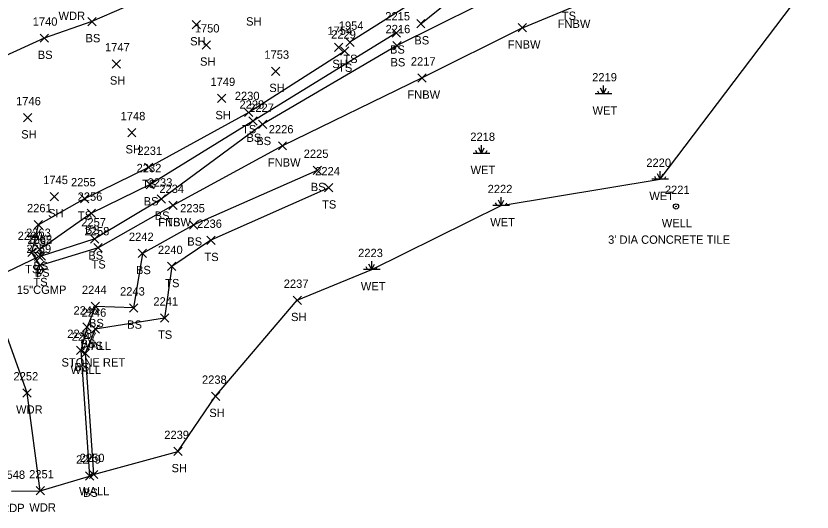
# Model space of a CAD drawing. Extents: x 1526508 to 1531550, y 369926 to 373082.
# Drawn here: x 1531142.8 to 1531334.3, y 370023.7 to 370143.1 of the extents above; entities that cross this region are included whole.
import ezdxf

# ---------------------------------------------------------------- set-up
doc = ezdxf.new("R2010")
doc.units = 0
for name, color, linetype in [('D_A', 7, 'Continuous'), ('D_C', 7, 'Continuous'), ('D_I', 7, 'Continuous'), ('D_TIC', 7, 'Continuous'), ('DCP', 7, 'Continuous'), ('L_A', 7, 'Continuous'), ('L_C', 7, 'Continuous'), ('L_I', 7, 'Continuous'), ('L_TIC', 7, 'Continuous'), ('LAWA', 7, 'Continuous'), ('LELB', 7, 'Continuous'), ('LFNC', 7, 'Continuous'), ('LSOGP', 7, 'Continuous'), ('LW', 7, 'Continuous'), ('LWET', 7, 'Continuous'), ('P_A', 7, 'Continuous'), ('P_I', 7, 'Continuous'), ('U_A', 7, 'Continuous'), ('U_C', 7, 'Continuous'), ('U_I', 7, 'Continuous'), ('UWW', 7, 'Continuous')]:
    doc.layers.add(name, color=color, linetype=linetype)

msp = doc.modelspace()

# ---------------------------------------------------------------- linework, layer by layer
at = {"layer": 'D_TIC'}
for points in [[(1531147.27, 370084.19), (1531149.27, 370086.19)], [(1531149.27, 370084.19), (1531147.27, 370086.19)]]:
    msp.add_lwpolyline(points, dxfattribs=at)
at = {"layer": 'DCP'}
msp.add_lwpolyline([(1531096.61, 370060.47), (1531148.27, 370085.19)], dxfattribs=at)
at = {"layer": 'L_TIC'}
for points in [[(1531160.06, 370140.76), (1531162.06, 370142.76)], [(1531162.06, 370140.76), (1531160.06, 370142.76)], [(1531185.18, 370140.01), (1531187.18, 370142.01)], [(1531187.18, 370140.01), (1531185.18, 370142.01)], [(1531239.15, 370140.24), (1531241.15, 370142.24)], [(1531241.15, 370140.24), (1531239.15, 370142.24)], [(1531263.6, 370139.25), (1531265.6, 370141.25)], [(1531265.6, 370139.25), (1531263.6, 370141.25)], [(1531233.29, 370138.03), (1531235.29, 370140.03)], [(1531235.29, 370138.03), (1531233.29, 370140.03)], [(1531148.58, 370136.75), (1531150.58, 370138.75)], [(1531150.58, 370136.75), (1531148.58, 370138.75)], [(1531187.55, 370135.12), (1531189.55, 370137.12)], [(1531189.55, 370135.12), (1531187.55, 370137.12)], [(1531222.1, 370135.77), (1531224.1, 370137.77)], [(1531224.1, 370135.77), (1531222.1, 370137.77)], [(1531219.37, 370134.56), (1531221.37, 370136.56)], [(1531221.37, 370134.56), (1531219.37, 370136.56)], [(1531220.84, 370133.65), (1531222.84, 370135.65)], [(1531222.84, 370133.65), (1531220.84, 370135.65)], [(1531233.42, 370134.95), (1531235.42, 370136.95)], [(1531235.42, 370134.95), (1531233.42, 370136.95)], [(1531165.88, 370130.57), (1531167.88, 370132.57)], [(1531167.88, 370130.57), (1531165.88, 370132.57)], [(1531204.21, 370128.79), (1531206.21, 370130.79)], [(1531206.21, 370128.79), (1531204.21, 370130.79)], [(1531239.44, 370127.17), (1531241.44, 370129.17)], [(1531241.44, 370127.17), (1531239.44, 370129.17)], [(1531191.25, 370122.24), (1531193.25, 370124.24)], [(1531193.25, 370122.24), (1531191.25, 370124.24)], [(1531197.75, 370118.86), (1531199.75, 370120.86)], [(1531199.75, 370118.86), (1531197.75, 370120.86)], [(1531144.55, 370117.6), (1531146.55, 370119.6)], [(1531146.55, 370117.6), (1531144.55, 370119.6)], [(1531198.78, 370116.78), (1531200.78, 370118.78)], [(1531200.78, 370116.78), (1531198.78, 370118.78)], [(1531201.13, 370116.01), (1531203.13, 370118.01)], [(1531203.13, 370116.01), (1531201.13, 370118.01)], [(1531169.64, 370114), (1531171.64, 370116)], [(1531171.64, 370114), (1531169.64, 370116)], [(1531205.88, 370110.83), (1531207.88, 370112.83)], [(1531207.88, 370110.83), (1531205.88, 370112.83)], [(1531173.68, 370105.65), (1531175.68, 370107.65)], [(1531175.68, 370105.65), (1531173.68, 370107.65)], [(1531214.23, 370104.93), (1531216.23, 370106.93)], [(1531216.23, 370104.93), (1531214.23, 370106.93)], [(1531174.05, 370101.49), (1531176.05, 370103.49)], [(1531176.05, 370101.49), (1531174.05, 370103.49)], [(1531216.99, 370100.73), (1531218.99, 370102.73)], [(1531218.99, 370100.73), (1531216.99, 370102.73)], [(1531151.01, 370098.62), (1531153.01, 370100.62)], [(1531153.01, 370098.62), (1531151.01, 370100.62)], [(1531158.26, 370098.08), (1531160.26, 370100.08)], [(1531160.26, 370098.08), (1531158.26, 370100.08)], [(1531176.7, 370098.03), (1531178.7, 370100.03)], [(1531178.7, 370098.03), (1531176.7, 370100.03)], [(1531179.52, 370096.48), (1531181.52, 370098.48)], [(1531181.52, 370096.48), (1531179.52, 370098.48)], [(1531179.52, 370096.48), (1531181.52, 370098.48)], [(1531181.52, 370096.48), (1531179.52, 370098.48)], [(1531159.93, 370094.61), (1531161.93, 370096.61)], [(1531161.93, 370094.61), (1531159.93, 370096.61)], [(1531147.18, 370091.85), (1531149.18, 370093.85)], [(1531149.18, 370091.85), (1531147.18, 370093.85)], [(1531147.18, 370091.85), (1531149.18, 370093.85)], [(1531149.18, 370091.85), (1531147.18, 370093.85)], [(1531184.52, 370091.81), (1531186.52, 370093.81)], [(1531186.52, 370091.81), (1531184.52, 370093.81)], [(1531160.73, 370088.44), (1531162.73, 370090.44)], [(1531162.73, 370088.44), (1531160.73, 370090.44)], [(1531188.68, 370088.09), (1531190.68, 370090.09)], [(1531190.68, 370088.09), (1531188.68, 370090.09)], [(1531147.5, 370085.91), (1531149.5, 370087.91)], [(1531149.5, 370085.91), (1531147.5, 370087.91)], [(1531147.5, 370085.91), (1531149.5, 370087.91)], [(1531149.5, 370085.91), (1531147.5, 370087.91)], [(1531161.53, 370086.3), (1531163.53, 370088.3)], [(1531163.53, 370086.3), (1531161.53, 370088.3)], [(1531145.59, 370085.17), (1531147.59, 370087.17)], [(1531147.59, 370085.17), (1531145.59, 370087.17)], [(1531147.84, 370084.31), (1531149.84, 370086.31)], [(1531149.84, 370084.31), (1531147.84, 370086.31)], [(1531172.2, 370084.94), (1531174.2, 370086.94)], [(1531174.2, 370084.94), (1531172.2, 370086.94)], [(1531147.56, 370082.05), (1531149.56, 370084.05)], [(1531149.56, 370082.05), (1531147.56, 370084.05)], [(1531179.26, 370081.79), (1531181.26, 370083.79)], [(1531181.26, 370081.79), (1531179.26, 370083.79)], [(1531160.89, 370072.17), (1531162.89, 370074.17)], [(1531162.89, 370072.17), (1531160.89, 370074.17)], [(1531209.44, 370073.64), (1531211.44, 370075.64)], [(1531211.44, 370073.64), (1531209.44, 370075.64)], [(1531170.07, 370071.8), (1531172.07, 370073.8)], [(1531172.07, 370071.8), (1531170.07, 370073.8)], [(1531177.52, 370069.38), (1531179.52, 370071.38)], [(1531179.52, 370069.38), (1531177.52, 370071.38)], [(1531158.87, 370067.22), (1531160.87, 370069.22)], [(1531160.87, 370067.22), (1531158.87, 370069.22)], [(1531160.86, 370066.7), (1531162.86, 370068.7)], [(1531162.86, 370066.7), (1531160.86, 370068.7)], [(1531160.86, 370066.7), (1531162.86, 370068.7)], [(1531162.86, 370066.7), (1531160.86, 370068.7)], [(1531157.37, 370061.59), (1531159.37, 370063.59)], [(1531159.37, 370061.59), (1531157.37, 370063.59)], [(1531158.43, 370060.89), (1531160.43, 370062.89)], [(1531160.43, 370060.89), (1531158.43, 370062.89)], [(1531144.43, 370051.36), (1531146.43, 370053.36)], [(1531146.43, 370051.36), (1531144.43, 370053.36)], [(1531189.78, 370050.55), (1531191.78, 370052.55)], [(1531191.78, 370050.55), (1531189.78, 370052.55)], [(1531180.71, 370037.25), (1531182.71, 370039.25)], [(1531182.71, 370037.25), (1531180.71, 370039.25)], [(1531160.45, 370031.71), (1531162.45, 370033.71)], [(1531162.45, 370031.71), (1531160.45, 370033.71)], [(1531159.49, 370031.33), (1531161.49, 370033.33)], [(1531161.49, 370031.33), (1531159.49, 370033.33)], [(1531147.63, 370027.78), (1531149.63, 370029.78)], [(1531149.63, 370027.78), (1531147.63, 370029.78)]]:
    msp.add_lwpolyline(points, dxfattribs=at)
at = {"layer": 'LAWA'}
msp.add_lwpolyline([(1531148.63, 370028.78), (1531145.43, 370052.36), (1531135.56, 370079.96), (1531135.23, 370090.89)], dxfattribs=at)
at = {"layer": 'LELB'}
for points in [[(1531365.84, 370210.96), (1531346.81, 370202.24), (1531320.04, 370188.54), (1531298.98, 370175.8), (1531270.91, 370160.47), (1531253.9, 370156.3), (1531223.1, 370136.77)], [(1531240.15, 370141.24), (1531255.53, 370153.74), (1531283.26, 370165.55), (1531305.03, 370178.46), (1531329.23, 370188.15), (1531348.16, 370200.01), (1531367.42, 370209.81)], [(1531210.97, 370157.64), (1531190.22, 370151.95), (1531176.55, 370148.6), (1531161.06, 370141.76), (1531149.58, 370137.75), (1531135.28, 370131.25)], [(1531263.26, 370150.37), (1531234.42, 370135.95), (1531202.13, 370117.01), (1531177.7, 370099.03), (1531161.73, 370089.44), (1531148.84, 370085.31), (1531148.5, 370086.91)], [(1531234.29, 370139.03), (1531199.78, 370117.78), (1531175.05, 370102.49), (1531160.93, 370095.61), (1531148.5, 370086.91)], [(1531221.84, 370134.65), (1531198.75, 370119.86), (1531174.68, 370106.65), (1531159.26, 370099.08), (1531148.18, 370092.85)], [(1531215.23, 370105.93), (1531185.52, 370092.81), (1531173.2, 370085.94), (1531171.07, 370072.8), (1531161.89, 370073.17), (1531159.87, 370068.22), (1531158.37, 370062.59), (1531160.49, 370032.33)], [(1531217.99, 370101.73), (1531189.68, 370089.09), (1531180.26, 370082.79), (1531178.52, 370070.38), (1531161.86, 370067.7)], [(1531180.52, 370097.48), (1531162.53, 370087.3), (1531148.56, 370083.05), (1531146.59, 370086.17), (1531148.18, 370092.85)]]:
    msp.add_lwpolyline(points, dxfattribs=at)
at = {"layer": 'LFNC'}
for points in [[(1531264.6, 370140.25), (1531276.59, 370145.24)], [(1531264.6, 370140.25), (1531240.44, 370128.17), (1531206.88, 370111.83), (1531180.52, 370097.48)]]:
    msp.add_lwpolyline(points, dxfattribs=at)
at = {"layer": 'LSOGP'}
msp.add_lwpolyline([(1531141.72, 370028.66), (1531148.63, 370028.78), (1531160.49, 370032.33), (1531161.45, 370032.71), (1531181.71, 370038.25), (1531190.78, 370051.55), (1531210.44, 370074.64), (1531228.34, 370082.05), (1531259.48, 370097.44), (1531297.73, 370103.77), (1531345.31, 370166.81)], dxfattribs=at)
at = {"layer": 'LW'}
msp.add_lwpolyline([(1531161.86, 370067.7), (1531159.43, 370061.89), (1531161.45, 370032.71)], dxfattribs=at)
at = {"layer": 'LWET'}
for p, q in [((1531284.06, 370124.35), (1531283.39, 370125.68)), ((1531284.06, 370124.35), (1531284.06, 370126.35)), ((1531284.06, 370124.35), (1531284.73, 370125.68)), ((1531286.06, 370124.35), (1531282.06, 370124.35)), ((1531283.06, 370124.35), (1531282.73, 370125.01)), ((1531285.06, 370124.35), (1531285.39, 370125.01)), ((1531253.74, 370110.02), (1531253.41, 370110.69)), ((1531254.74, 370110.02), (1531254.07, 370111.35)), ((1531254.74, 370110.02), (1531254.74, 370112.02)), ((1531254.74, 370110.02), (1531255.41, 370111.35)), ((1531255.74, 370110.02), (1531256.07, 370110.69)), ((1531256.74, 370110.02), (1531252.74, 370110.02)), ((1531297.73, 370103.77), (1531297.06, 370105.11)), ((1531297.73, 370103.77), (1531297.73, 370105.77)), ((1531297.73, 370103.77), (1531298.4, 370105.11)), ((1531299.73, 370103.77), (1531295.73, 370103.77)), ((1531296.73, 370103.77), (1531296.4, 370104.44)), ((1531298.73, 370103.77), (1531299.06, 370104.44)), ((1531259.48, 370097.44), (1531258.81, 370098.78)), ((1531259.48, 370097.44), (1531259.48, 370099.44)), ((1531259.48, 370097.44), (1531260.14, 370098.78)), ((1531261.48, 370097.44), (1531257.48, 370097.44)), ((1531258.48, 370097.44), (1531258.14, 370098.11)), ((1531260.48, 370097.44), (1531260.81, 370098.11)), ((1531228.34, 370082.05), (1531228.34, 370084.05)), ((1531230.34, 370082.05), (1531226.34, 370082.05)), ((1531227.34, 370082.05), (1531227.01, 370082.72)), ((1531228.34, 370082.05), (1531227.68, 370083.38)), ((1531228.34, 370082.05), (1531229.01, 370083.38)), ((1531229.34, 370082.05), (1531229.68, 370082.72))]:
    msp.add_line(p, q, dxfattribs=at)
at = {"layer": 'UWW'}
for radius in [0.625, 0.0833]:
    msp.add_circle((1531301.53, 370097.25), radius, dxfattribs=at)

# ---------------------------------------------------------------- texts
at = {"layer": 'D_A'}
msp.add_text('P', height=2, dxfattribs=at).set_placement((1531147.65, 370080.19))
at = {"layer": 'D_C'}
msp.add_text('15"CGMP', height=2, dxfattribs=at).set_placement((1531142.97, 370076.19))
at = {"layer": 'D_I'}
msp.add_text('1565', height=2, dxfattribs=at).set_placement((1531145.53, 370088.19))
at = {"layer": 'L_A'}
for s, p in [('WDR', (1531153.01, 370142.14)), ('SH', (1531198.12, 370140.79)), ('TS', (1531274.06, 370142.15)), ('FNBW', (1531273.06, 370140.24)), ('BS', (1531159.5, 370136.76)), ('SH', (1531184.67, 370136.01)), ('BS', (1531238.59, 370136.24)), ('FNBW', (1531261.07, 370135.25)), ('BS', (1531232.73, 370134.03)), ('BS', (1531148.02, 370132.75)), ('TS', (1531221.51, 370131.77)), ('SH', (1531187.04, 370131.12)), ('SH', (1531218.86, 370130.56)), ('TS', (1531220.25, 370129.65)), ('BS', (1531232.86, 370130.95)), ('SH', (1531165.37, 370126.57)), ('SH', (1531203.7, 370124.79)), ('FNBW', (1531236.92, 370123.17)), ('SH', (1531190.74, 370118.24)), ('WET', (1531281.44, 370119.35)), ('TS', (1531197.16, 370114.86)), ('SH', (1531144.04, 370113.6)), ('BS', (1531198.22, 370112.78)), ('BS', (1531200.57, 370112.01)), ('SH', (1531169.12, 370110)), ('FNBW', (1531203.36, 370106.83)), ('WET', (1531252.12, 370105.02)), ('TS', (1531173.08, 370101.65)), ('BS', (1531213.68, 370100.93)), ('WET', (1531295.11, 370098.77)), ('BS', (1531173.49, 370097.49)), ('TS', (1531216.4, 370096.73)), ('SH', (1531150.5, 370094.62)), ('TS', (1531157.67, 370094.08)), ('BS', (1531176.14, 370094.03)), ('FNBW', (1531176.99, 370092.48)), ('TS', (1531178.93, 370092.48)), ('WET', (1531256.85, 370092.44)), ('BS', (1531159.37, 370090.61)), ('TS', (1531146.58, 370087.85)), ('TS', (1531146.58, 370087.85)), ('BS', (1531183.97, 370087.81)), ('BS', (1531160.17, 370084.44)), ('TS', (1531188.09, 370084.09)), ('BS', (1531146.95, 370081.91)), ('BS', (1531146.95, 370081.91)), ('TS', (1531160.94, 370082.3)), ('TS', (1531144.99, 370081.17)), ('BS', (1531147.28, 370080.31)), ('BS', (1531171.64, 370080.94)), ('TS', (1531146.97, 370078.05)), ('TS', (1531178.67, 370077.79)), ('WET', (1531225.72, 370077.05)), ('BS', (1531160.33, 370068.17)), ('SH', (1531208.93, 370069.64)), ('BS', (1531169.51, 370067.8)), ('TS', (1531176.93, 370065.38)), ('WALL', (1531158.35, 370062.7)), ('BS', (1531158.31, 370063.22)), ('TS', (1531160.27, 370062.7)), ('WALL', (1531155.92, 370056.89)), ('BS', (1531156.81, 370057.59)), ('WDR', (1531142.8, 370047.36)), ('SH', (1531189.27, 370046.55)), ('SH', (1531180.2, 370033.25)), ('WALL', (1531157.94, 370027.71)), ('BS', (1531158.93, 370027.33)), ('WDR', (1531145.99, 370023.78))]:
    msp.add_text(s, height=2, dxfattribs=at).set_placement(p)
at = {"layer": 'L_C'}
msp.add_text('STONE RET', height=2, dxfattribs=at).set_placement((1531153.73, 370058.7))
at = {"layer": 'L_I'}
for s, p in [('2215', (1531231.6, 370142.03)), ('1740', (1531146.8, 370140.75)), ('1750', (1531185.77, 370139.12)), ('1954', (1531220.41, 370139.77)), ('2216', (1531231.67, 370138.95)), ('1754', (1531217.68, 370138.56)), ('2229', (1531218.57, 370137.65)), ('1747', (1531164.19, 370134.57)), ('1753', (1531202.52, 370132.79)), ('2217', (1531237.75, 370131.17)), ('1749', (1531189.55, 370126.24)), ('2219', (1531281.36, 370127.35)), ('2230', (1531195.4, 370122.86)), ('1746', (1531142.8, 370121.6)), ('2228', (1531196.52, 370120.78)), ('2227', (1531198.87, 370120.01)), ('1748', (1531167.94, 370118)), ('2226', (1531203.57, 370114.83)), ('2218', (1531252.05, 370113.02)), ('2231', (1531171.98, 370109.65)), ('2225', (1531211.98, 370108.93)), ('2220', (1531294.38, 370106.77)), ('2232', (1531171.79, 370105.49)), ('2224', (1531214.74, 370104.73)), ('1745', (1531149.32, 370102.62)), ('2255', (1531156.01, 370102.08)), ('2233', (1531174.44, 370102.03)), ('2234', (1531177.26, 370100.48)), ('2234', (1531177.26, 370100.48)), ('2222', (1531256.22, 370100.44)), ('2256', (1531157.61, 370098.61)), ('2261', (1531145.43, 370095.85)), ('2261', (1531145.43, 370095.85)), ('2235', (1531182.26, 370095.81)), ('2257', (1531158.47, 370092.44)), ('2236', (1531186.36, 370092.09)), ('2260', (1531143.19, 370089.17)), ('2263', (1531145.2, 370089.91)), ('2263', (1531145.2, 370089.91)), ('2258', (1531159.27, 370090.3)), ('2262', (1531145.54, 370088.31)), ('2242', (1531169.94, 370088.94)), ('2259', (1531145.29, 370086.05)), ('2240', (1531176.92, 370085.79)), ('2223', (1531225.08, 370085.05)), ('2237', (1531207.18, 370077.64)), ('2244', (1531158.63, 370076.17)), ('2243', (1531167.81, 370075.8)), ('2241', (1531175.82, 370073.38)), ('2245', (1531156.61, 370071.22)), ('2246', (1531158.55, 370070.7)), ('2246', (1531158.55, 370070.7)), ('2248', (1531155.11, 370065.59)), ('2247', (1531156.17, 370064.89)), ('2252', (1531142.18, 370055.36)), ('2238', (1531187.52, 370054.55)), ('2239', (1531178.44, 370041.25)), ('2250', (1531158.11, 370035.71)), ('2249', (1531157.22, 370035.33)), ('2251', (1531145.94, 370031.78))]:
    msp.add_text(s, height=2, dxfattribs=at).set_placement(p)
at = {"layer": 'P_A'}
msp.add_text('RDP', height=2, dxfattribs=at).set_placement((1531139.21, 370023.66))
at = {"layer": 'P_I'}
msp.add_text('1548', height=2, dxfattribs=at).set_placement((1531139.02, 370031.66))
at = {"layer": 'U_A'}
msp.add_text('WELL', height=2, dxfattribs=at).set_placement((1531298.1, 370092.25))
at = {"layer": 'U_C'}
msp.add_text("3' DIA CONCRETE TILE", height=2, dxfattribs=at).set_placement((1531285.19, 370088.25))
at = {"layer": 'U_I'}
msp.add_text('2221', height=2, dxfattribs=at).set_placement((1531298.84, 370100.25))

doc.saveas('drawing.dxf')
